(* Logix 5000 project; controller L32E vendor 1 type 14 code 65 rev 16.20; software revision 16.03 *)

TASK MainTask (continuous, watchdog 500 ms) : MainProgram

MODULES
   Controller : vendor 1 type 14 code 65 (CompactLogixL35Controller 0, rev 16.20)
      LocalENB : 1769-L35E Ethernet Port (CompactLogixL35Ethernet 1, rev 16.3)
      Local : CompactBus (CompactVirtualAdapter 3, rev 16.1, Input RPI 2 ms)
         DPS : 1769-MODULE (Compact 1, rev 1.1, Output RPI 2 ms)   // 1769-DPS
END_MODULES

TYPE APP_CONSTANT_PATTERN :   // Constant Values Used for DPV1 Alarm and ExtDiagData
STRUCT
   UserAlarmData : SINT[32];   // Constants for Alarm Data
END_STRUCT
END_TYPE

TYPE APP_DPV1_PROG_CONTROL :   // Program Control Bits
STRUCT
   MainInitDone : BOOL;   // Main Initialization Complete
   Dpv1ReadRespInProgress : BOOL;   // DPV1 Read Response in Progress
   Dpv1WriteRespInProgress : BOOL;   // DPV1 Write Response in Progress
   Dpv1AlarmReqSend : BOOL;   // DPV1 Alarm Request Flag
   Dpv1AlarmReqInProgress : BOOL;   // DPV1 Alarm Request in Progress
   DpsDiagReqSend : BOOL;   // DPS Diagnostics Request Flag
   DpsDiagReqInProgress : BOOL;   // DPS Diagnostic Request in Progress
   Reserved0 : BOOL;   // Reserved
   Reserved1 : BOOL;   // Reserved
   Reserved2 : BOOL;   // Reserved
   Reserved3 : BOOL;   // Reserved
   Reserved4 : BOOL;   // Reserved
   Reserved5 : BOOL;   // Reserved
   Reserved6 : BOOL;   // Reserved
   Reserved7 : BOOL;   // Reserved
   Reserved8 : BOOL;   // Reserved
   DPV1RWIndCnt : SINT;   // DPV1 R/W Indication Counter
END_STRUCT
END_TYPE

TYPE APP_DPV1_STAT_COUNTER :   // DPV1 Status Counter
STRUCT
   NumReadWrite : DINT;   // Number of DPV1 Read Write Response Sent
   ReadRespPos : DINT;   // Number of DPV1 Read Response Successful
   ReadRespNeg : DINT;   // Number of DPV1 Read Response Failed
   WriteRespPos : DINT;   // Number of DPV1 Write Response Successful
   WriteRespNeg : DINT;   // Number of DPV1 Write Response Failed
   NumAlarmRequest : DINT;   // Number of DPV1 Alarm Requests sent
   AlarmRequestPos : DINT;   // Number of DPV1 Alarm Requests Successful
   AlarmRequestNeg : DINT;   // Number of DPV1 Alarm Requests Failed
   NumDiagReq : DINT;   // Number of Diagnostic Reports Sent
   DiagReqPos : DINT;   // Number of Diagnostic Report Successful
   DiagReqNeg : DINT;   // Number of Diagnostic Report Failed
END_STRUCT
END_TYPE

TYPE DPS_DEV_COMMAND_REGISTER :   // Device Command Register
STRUCT
   Reserved0 : BOOL;   // Reserved
   Reserved1 : BOOL;   // Reserved
   Reserved2 : BOOL;   // Reserved
   Reserved3 : BOOL;   // Reserved
   Reserved4 : BOOL;   // Reserved
   NRdy : BOOL;   // Application Not Ready
   Init : BOOL;   // Init ( Warm boot )
   Reset : BOOL;   // Reset ( Cold boot )
   Reserved5 : SINT;   // Reserved
   Reserved6 : SINT;   // Reserved
   ExtStaSelect : SINT;   // Extra Status Select
END_STRUCT
END_TYPE

TYPE DPS_DEV_STATUS_REGISTER :   // Device Status Register
STRUCT
   Reserved0 : BOOL;   // Reserved
   Reserved1 : BOOL;   // Reserved
   Reserved2 : BOOL;   // Reserved
   Reserved3 : BOOL;   // Reserved
   Reserved4 : BOOL;   // Reserved
   Com : BOOL;   // Communication
   Run : BOOL;   // Running
   Rdy : BOOL;   // Ready
   Reserved5 : SINT;   // Reserved
   Reserved6 : SINT;   // Reserved
   Reserved7 : SINT;   // Reserved
END_STRUCT
END_TYPE

TYPE DPS_DIAGNOSTIC_CONFIRM :   // DPS Diagnostics Confirmation
STRUCT
   Reserved1 : INT;   // Reserved
   Reserved2 : INT;   // Reserved
   Answer : SINT;   // Answer of Diag Req
   Failure : SINT;   // Failure
   Reserved4 : INT;   // Reserved
   Reserved5 : INT;   // Reserved
   Reserved6 : INT;   // Reserved
   Reserved7 : SINT;   // Reserved
   ExtDiagDataCnt : SINT;   // Extended Diagnostics Data Count
   Mode : SINT;   // Mode
   Function : SINT;   // Function
END_STRUCT
END_TYPE

TYPE DPS_DIAGNOSTIC_REQUEST :   // DPS Diagnostics Request
STRUCT
   Reserved1 : INT;   // Reserved
   Reserved2 : INT;   // Reserved
   Reserved3 : INT;   // Reserved
   Command : SINT;   // Command for Diag Req = 24
   Reserved4 : SINT;   // Reserved
   Reserved5 : INT;   // Reserved
   Reserved6 : INT;   // Reserved
   Reserved7 : SINT;   // Reserved
   ExtDiagDataCnt : SINT;   // Number of ext. diag data
   Mode : SINT;   // Diag mode: (0 = default, 1 = suppress Ext.DiagBit)
   Function : SINT;   // Send diag once (fix 18)
   DiagData : SINT[32];   // Extended diag data (format see PROFIBUS Norm)
END_STRUCT
END_TYPE

TYPE DPS_DPV1C1_ALARM_CONFIRM :   // DPV1 Alarm Confirmation
STRUCT
   Reserved1 : INT;   // Reserved
   Reserved2 : INT;   // Reserved
   Answer : SINT;   // DPV1 Alarm Answer Flag
   Failure : SINT;   // DPV1 Alarm Failure
   Reserved3 : INT;   // Reserved
   Reserved4 : INT;   // Reserved
   SlotNumber : INT;   // DPV1 Alarm Slot Number
   SequenceNumber : SINT;   // DPV1 Alarm Sequence Number
   DataCnt : SINT;   // DPV1 Alarm Data Count
   AlarmType : SINT;   // DPV1 Alarm Type
   Specifier : SINT;   // DPV1 Alarm Specifier
END_STRUCT
END_TYPE

TYPE DPS_DPV1C1_ALARM_REQUEST :   // DPV1 Alarm Request
STRUCT
   Reserved1 : INT;   // Reserved
   Reserved2 : INT;   // Reserved
   Reserved3 : INT;   // Reserved
   Command : SINT;   // DPV1 Alarm Command
   Reserved4 : SINT;   // Reserved
   Reserved5 : INT;   // Reserved
   SlotNumber : INT;   // DPV1 Alarm Slot Number
   SequenceNumber : SINT;   // DPV1 Alarm Sequence Number
   DataCnt : SINT;   // DPV1 Alarm Data Count
   AlarmType : SINT;   // DPV1 Alarm Type
   Specifier : SINT;   // DPV1 Alarm Specifier
   AlarmData : SINT[28];   // DPV1 Alarm Data Array
END_STRUCT
END_TYPE

TYPE DPS_DPV1C1_RW_INDICATION :   // DPV1 C1 Read/Write Indication
STRUCT
   ReadReq : BOOL;   // Indicates a Read request
   WriteReq : BOOL;   // Indicates a Write request
   Reserved2 : BOOL;   // Reserved
   Reserved3 : BOOL;   // Reserved
   Reserved4 : BOOL;   // Reserved
   Reserved5 : BOOL;   // Reserved
   Reserved6 : BOOL;   // Reserved
   Reserved7 : BOOL;   // Reserved
   RwCnt : SINT;   // ReadWrite indication counter
   MaAdr : SINT;   // Address of reqesting master
   Slot : SINT;   // Requested Slot Number
   Index : SINT;   // Requested Index
   DataLen : SINT;   // Requested Data Length
   Reserved8 : SINT;   // Reserved
   Reserved9 : SINT;   // Reserved
END_STRUCT
END_TYPE

TYPE DPS_DPV1C1_RW_RESP_CONFIRM :   // DPV1 Class 1 Read/Write Confirmation
STRUCT
   Reserved1 : INT;   // Reserved
   Reserved2 : INT;   // Reserved
   Answer : SINT;   // DPV1 R/W Answer
   Failure : SINT;   // DPV1 R/W Failure
   Reserved3 : INT;   // Reserved
   RwResp : SINT;   // Read Resp (=1) or Write Resp (=2)
   Reserved4 : SINT;   // Reserved
   MaAdr : SINT;   // Reply of reqesting Master Address
   Slot : SINT;   // Reply of requested Slot Number
   Index : SINT;   // Reply of requested Index
   DataLen : SINT;   // Number of requested data
   ErrCode1 : SINT;   // Reply of Error code 1 according to DPV1
   ErrCode2 : SINT;   // Reply of Error code 2 according to DPV1
   RWRespData : SINT[240];   // DPV1 Write data
END_STRUCT
END_TYPE

TYPE DPS_DPV1C1_RW_RESP_REQUEST :   // DPV1 Class 1 Read/Write Response Request
STRUCT
   Reserved1 : INT;   // Reserved
   Reserved2 : INT;   // Reserved
   Reserved3 : INT;   // Reserved
   Command : SINT;   // DPV1 ReadWrite Resp. Request (=17)
   Reserved4 : SINT;   // Reserved
   RwResp : SINT;   // Read Resp (=1) or Write Resp (=2)
   Reserved5 : SINT;   // Reserved
   MaAdr : SINT;   // Reply of reqesting Master Address
   Slot : SINT;   // Reply of requested Slot Number
   Index : SINT;   // Reply of requested Index
   DataLen : SINT;   // Reply of requested number of data
   ErrCode1 : SINT;   // Error code 1 according to DPV1
   ErrCode2 : SINT;   // Error code 2 according to DPV1
   RWRespData : SINT[240];   // DPV1 Read response data
END_STRUCT
END_TYPE

TYPE DPS_FW_REVISION :   // Firmware Major/Minor Revision
STRUCT
   FwMinor : SINT;   // Firmware Minor Revison
   FwMajor : SINT;   // Firmware Major Revison
   Reserved : INT;   // Reserved
END_STRUCT
END_TYPE

TYPE DPS_INPUT_ARRAY :   // DPS Input Array
STRUCT
   DevStaReg : DPS_DEV_STATUS_REGISTER;   // Device Status Registers
   FwRev : DPS_FW_REVISION;   // Firmware Revision
   StaField : DPS_STATUS_FIELD;   // DPS Status Registers
   PBOutputData : SINT[380];   // PROFIBUS Output Data from Matser
END_STRUCT
END_TYPE

TYPE DPS_MODULE_DEF :
STRUCT
   AppConstPattern : APP_CONSTANT_PATTERN;   // Constant Values used for DPV1 Alarm and ExtDiagData
   AppCtrl : APP_DPV1_PROG_CONTROL;   // Program Control Bits
   AppStatCnt : APP_DPV1_STAT_COUNTER;   // DPV1 Status Counter
   DiagCnf : DPS_DIAGNOSTIC_CONFIRM;   // DPS Diagnostics Confirmation
   DiagReq : DPS_DIAGNOSTIC_REQUEST;   // DPS Diagnostics Request
   DpsInputArray : DPS_INPUT_ARRAY;   // DPS Input Array
   DpsOutputArray : DPS_OUTPUT_ARRAY;   // DPS Output Array
   Dpv1AlarmCnf : DPS_DPV1C1_ALARM_CONFIRM;   // DPV1 Alarm Confirmation
   Dpv1AlarmReq : DPS_DPV1C1_ALARM_REQUEST;   // DPV1 Alarm Request
   DPV1RWDataBuffer : SINT[240];   // Buffer for DPV1 Data
   Dpv1RWRespCnf : DPS_DPV1C1_RW_RESP_CONFIRM;   // DPV1 Class 1 Read/Write Confirmation
   Dpv1RWRespReq : DPS_DPV1C1_RW_RESP_REQUEST;   // DPV1 Class 1 Read/Write Response Request
END_STRUCT
END_TYPE

TYPE DPS_OUTPUT_ARRAY :   // DPS Output Array
STRUCT
   DevCmdReg : DPS_DEV_COMMAND_REGISTER;   // Device Command Register
   PBInputData : SINT[244];   // PROFIBIBUS Input Data for Master
END_STRUCT
END_TYPE

TYPE DPS_STATUS_FIELD :   // DPS Status Field
STRUCT
   ExtStaSelect : INT;   // Extended Status Select
   ExtStaLen : INT;   // Extended Status Length
   Baudrate : INT;   // Slave Baudrate
   Busaddress : SINT;   // Slave Bus Address
   UserFlags : SINT;   // User Flags
   Ident : INT;   // Slave Ident Number
   TaskState : INT;   // Slave Task State
   InputDataLen : INT;   // Slave Input Data Length
   OutputDataLen : INT;   // Slave Output Data Length
   ErrorCount : INT;   // Slave Error Count
   LastError : SINT;   // Slave Last Error
   Pad : SINT;   // Reserved
   WatchdogTime : INT;   // Slave Watchdog Time
   IrqCounter : INT;   // Slave Interrupt Counter
   C1Ind : DPS_DPV1C1_RW_INDICATION;   // DPV1 Class 1 Indication Registers
   ExtStatusInfo : SINT[96];   // Extened Status Information
END_STRUCT
END_TYPE

ADD_ON_INSTRUCTION AOIPS69DPS   (* revision 1.1 *)
// Add-On instruction for the PS69-DPS module
// Revision note:
// Added viewing capability for the Add_On Instruction
VAR_IN_OUT
   Connection_Input : INT[190]; {required}   // Connect to module input image
   Connection_Output : INT[124]; {required}   // Connect to module output image
   PS69DPS : DPS_MODULE_DEF; {required}   // Main controller tag
   DiagReqMsg : MESSAGE; {required}
   Dpv1AlarmMsg : MESSAGE; {required}
   Dpv1RWMsg : MESSAGE; {required}
END_VAR

ROUTINE Logic   (* ladder *)
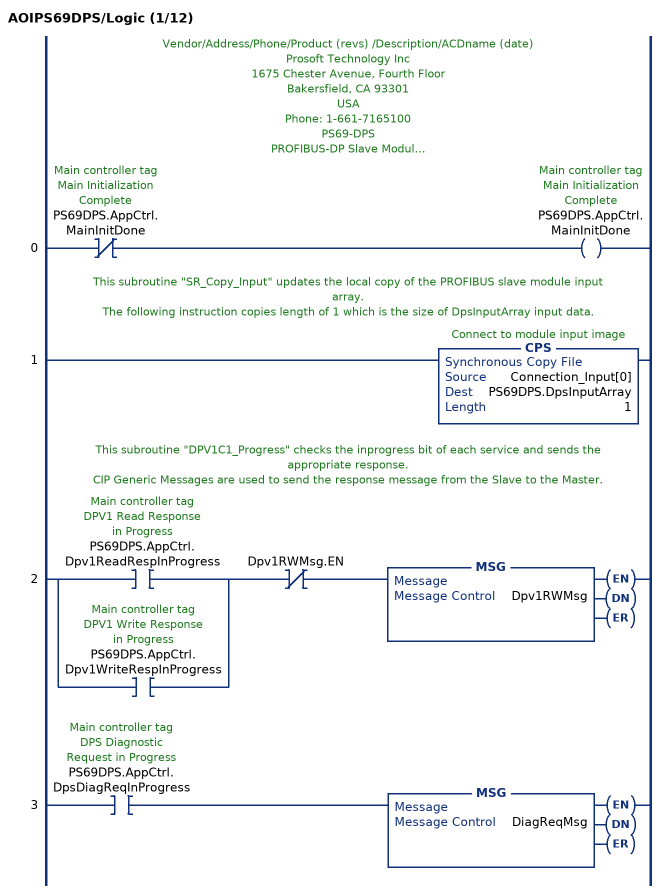
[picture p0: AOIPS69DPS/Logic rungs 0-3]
   // Vendor/Address/Phone/Product (revs) /Description/ACDname (date)
   // Prosoft Technology Inc
   // 1675 Chester Avenue, Fourth Floor
   // Bakersfield, CA 93301
   // USA
   // Phone: 1-661-7165100
   // PS69-DPS
   // PROFIBUS-DP Slave Module
   // PS69_DPS_messaging_L32E.ACD (Rev1.0) (07/28/05)
   // Although this program has been developed with great care and intensively tested,
   // Prosoft Technology Inc cannot guarantee the suitability of this program
   // for any purpose not confirmed by us in writing.
   // We reserve the right to modify our products and their specifications at any time in as far as this contributes to technical progress.
   // The version of the manual supplied with the program applies.
   // This program is a basic example RSLogix5000 project used for sending PROFIBUS messages to the communication module "PS69-DPS". This project provides an example for every supported PROFIBUS message by the module.
   // For detailed information about the these messages (functionality, parameters, error codes etc. ) refer to the module User Manual document.
   // This Rung calls all init routines for one time, to initialize the PROFIBUS commands.
   0: XIO(PS69DPS.AppCtrl.MainInitDone)OTE(PS69DPS.AppCtrl.MainInitDone);
   // This subroutine "SR_Copy_Input" updates the local copy of the PROFIBUS slave module input array.
   // The following instruction copies length of 1 which is the size of DpsInputArray input data.
   1: CPS(Connection_Input[0],PS69DPS.DpsInputArray,1);
   // This subroutine "DPV1C1_Progress" checks the inprogress bit of each service and sends the appropriate response.
   // CIP Generic Messages are used to send the response message from the Slave to the Master.
   2: [XIC(PS69DPS.AppCtrl.Dpv1ReadRespInProgress) ,XIC(PS69DPS.AppCtrl.Dpv1WriteRespInProgress) ]XIO(Dpv1RWMsg.EN)MSG(Dpv1RWMsg);
   3: XIC(PS69DPS.AppCtrl.DpsDiagReqInProgress)MSG(DiagReqMsg);
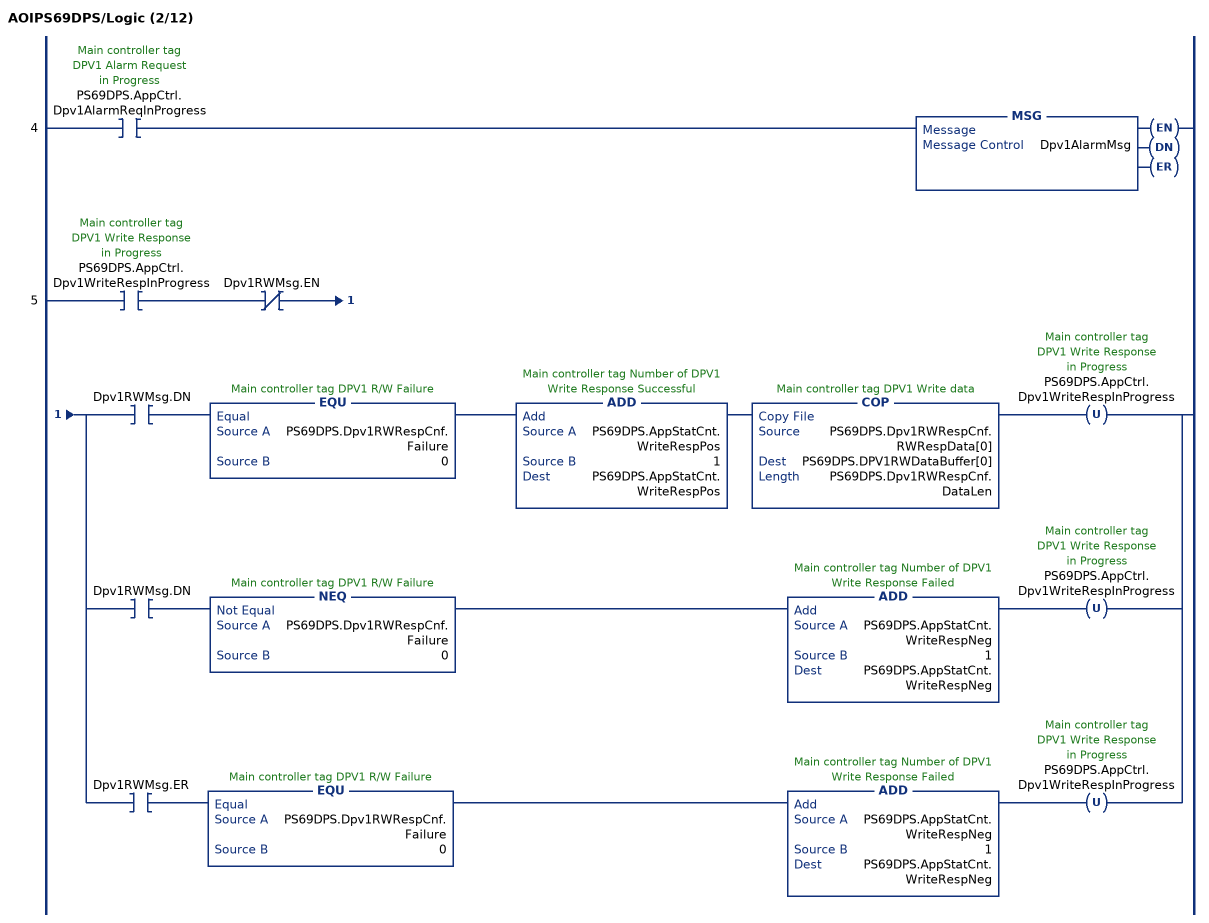
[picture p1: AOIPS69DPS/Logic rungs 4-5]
   4: XIC(PS69DPS.AppCtrl.Dpv1AlarmReqInProgress)MSG(Dpv1AlarmMsg);
   5: XIC(PS69DPS.AppCtrl.Dpv1WriteRespInProgress)XIO(Dpv1RWMsg.EN)[XIC(Dpv1RWMsg.DN) EQU(PS69DPS.Dpv1RWRespCnf.Failure,0) ADD(PS69DPS.AppStatCnt.WriteRespPos,1,PS69DPS.AppStatCnt.WriteRespPos) COP(PS69DPS.Dpv1RWRespCnf.RWRespData[0],PS69DPS.DPV1RWDataBuffer[0],PS69DPS.Dpv1RWRespCnf.DataLen) OTU(PS69DPS.AppCtrl.Dpv1WriteRespInProgress) ,XIC(Dpv1RWMsg.DN) NEQ(PS69DPS.Dpv1RWRespCnf.Failure,0) ADD(PS69DPS.AppStatCnt.WriteRespNeg,1,PS69DPS.AppStatCnt.WriteRespNeg) OTU(PS69DPS.AppCtrl.Dpv1WriteRespInProgress) ,XIC(Dpv1RWMsg.ER) EQU(PS69DPS.Dpv1RWRespCnf.Failure,0) ADD(PS69DPS.AppStatCnt.WriteRespNeg,1,PS69DPS.AppStatCnt.WriteRespNeg) OTU(PS69DPS.AppCtrl.Dpv1WriteRespInProgress) ];
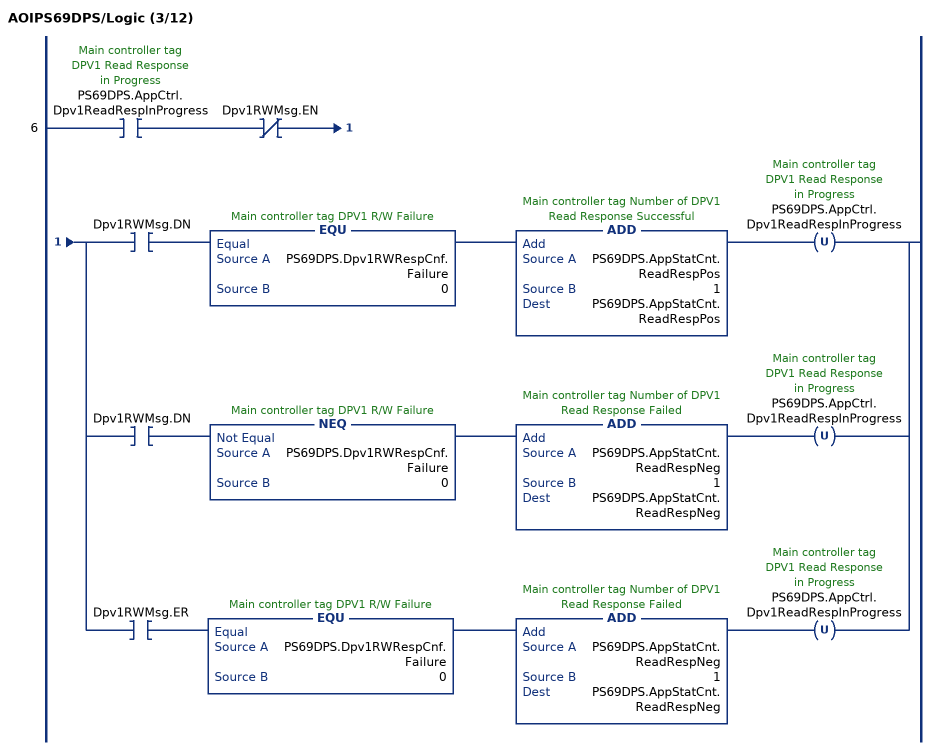
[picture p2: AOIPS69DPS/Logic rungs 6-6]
   6: XIC(PS69DPS.AppCtrl.Dpv1ReadRespInProgress)XIO(Dpv1RWMsg.EN)[XIC(Dpv1RWMsg.DN) EQU(PS69DPS.Dpv1RWRespCnf.Failure,0) ADD(PS69DPS.AppStatCnt.ReadRespPos,1,PS69DPS.AppStatCnt.ReadRespPos) OTU(PS69DPS.AppCtrl.Dpv1ReadRespInProgress) ,XIC(Dpv1RWMsg.DN) NEQ(PS69DPS.Dpv1RWRespCnf.Failure,0) ADD(PS69DPS.AppStatCnt.ReadRespNeg,1,PS69DPS.AppStatCnt.ReadRespNeg) OTU(PS69DPS.AppCtrl.Dpv1ReadRespInProgress) ,XIC(Dpv1RWMsg.ER) EQU(PS69DPS.Dpv1RWRespCnf.Failure,0) ADD(PS69DPS.AppStatCnt.ReadRespNeg,1,PS69DPS.AppStatCnt.ReadRespNeg) OTU(PS69DPS.AppCtrl.Dpv1ReadRespInProgress) ];
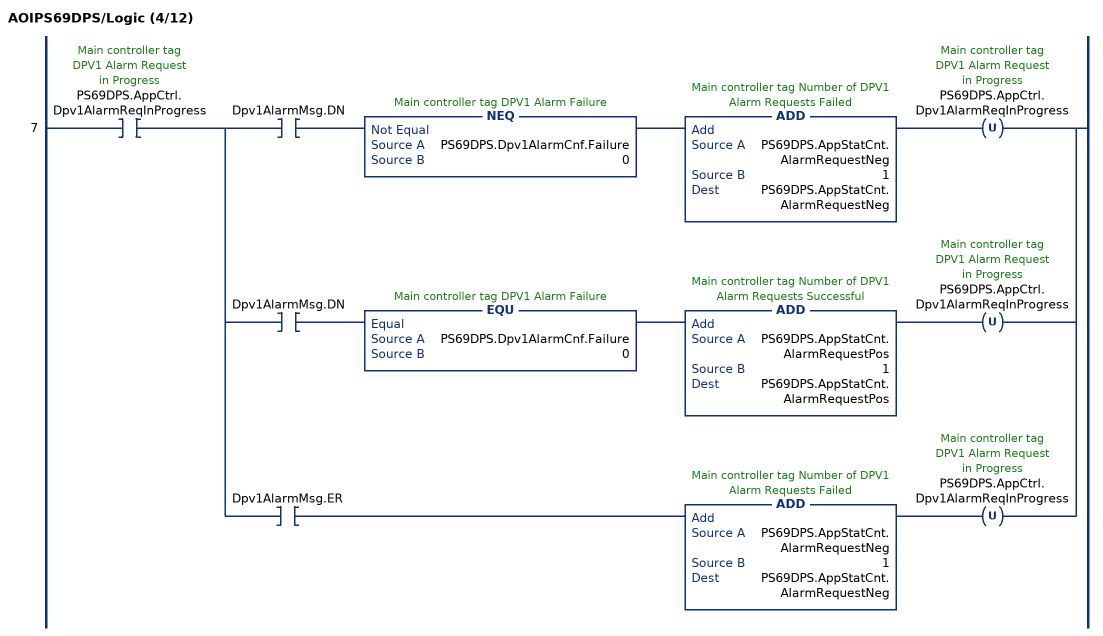
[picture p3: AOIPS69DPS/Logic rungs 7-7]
   7: XIC(PS69DPS.AppCtrl.Dpv1AlarmReqInProgress)[XIC(Dpv1AlarmMsg.DN) NEQ(PS69DPS.Dpv1AlarmCnf.Failure,0) ADD(PS69DPS.AppStatCnt.AlarmRequestNeg,1,PS69DPS.AppStatCnt.AlarmRequestNeg) OTU(PS69DPS.AppCtrl.Dpv1AlarmReqInProgress) ,XIC(Dpv1AlarmMsg.DN) EQU(PS69DPS.Dpv1AlarmCnf.Failure,0) ADD(PS69DPS.AppStatCnt.AlarmRequestPos,1,PS69DPS.AppStatCnt.AlarmRequestPos) OTU(PS69DPS.AppCtrl.Dpv1AlarmReqInProgress) ,XIC(Dpv1AlarmMsg.ER) ADD(PS69DPS.AppStatCnt.AlarmRequestNeg,1,PS69DPS.AppStatCnt.AlarmRequestNeg) OTU(PS69DPS.AppCtrl.Dpv1AlarmReqInProgress) ];
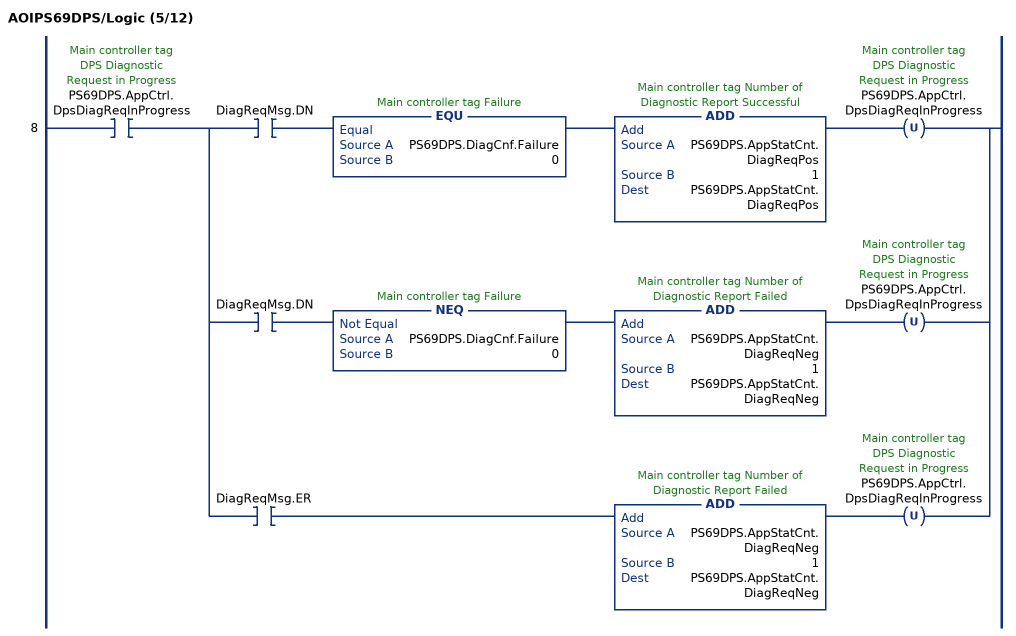
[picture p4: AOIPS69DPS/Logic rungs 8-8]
   8: XIC(PS69DPS.AppCtrl.DpsDiagReqInProgress)[XIC(DiagReqMsg.DN) EQU(PS69DPS.DiagCnf.Failure,0) ADD(PS69DPS.AppStatCnt.DiagReqPos,1,PS69DPS.AppStatCnt.DiagReqPos) OTU(PS69DPS.AppCtrl.DpsDiagReqInProgress) ,XIC(DiagReqMsg.DN) NEQ(PS69DPS.DiagCnf.Failure,0) ADD(PS69DPS.AppStatCnt.DiagReqNeg,1,PS69DPS.AppStatCnt.DiagReqNeg) OTU(PS69DPS.AppCtrl.DpsDiagReqInProgress) ,XIC(DiagReqMsg.ER) ADD(PS69DPS.AppStatCnt.DiagReqNeg,1,PS69DPS.AppStatCnt.DiagReqNeg) OTU(PS69DPS.AppCtrl.DpsDiagReqInProgress) ];
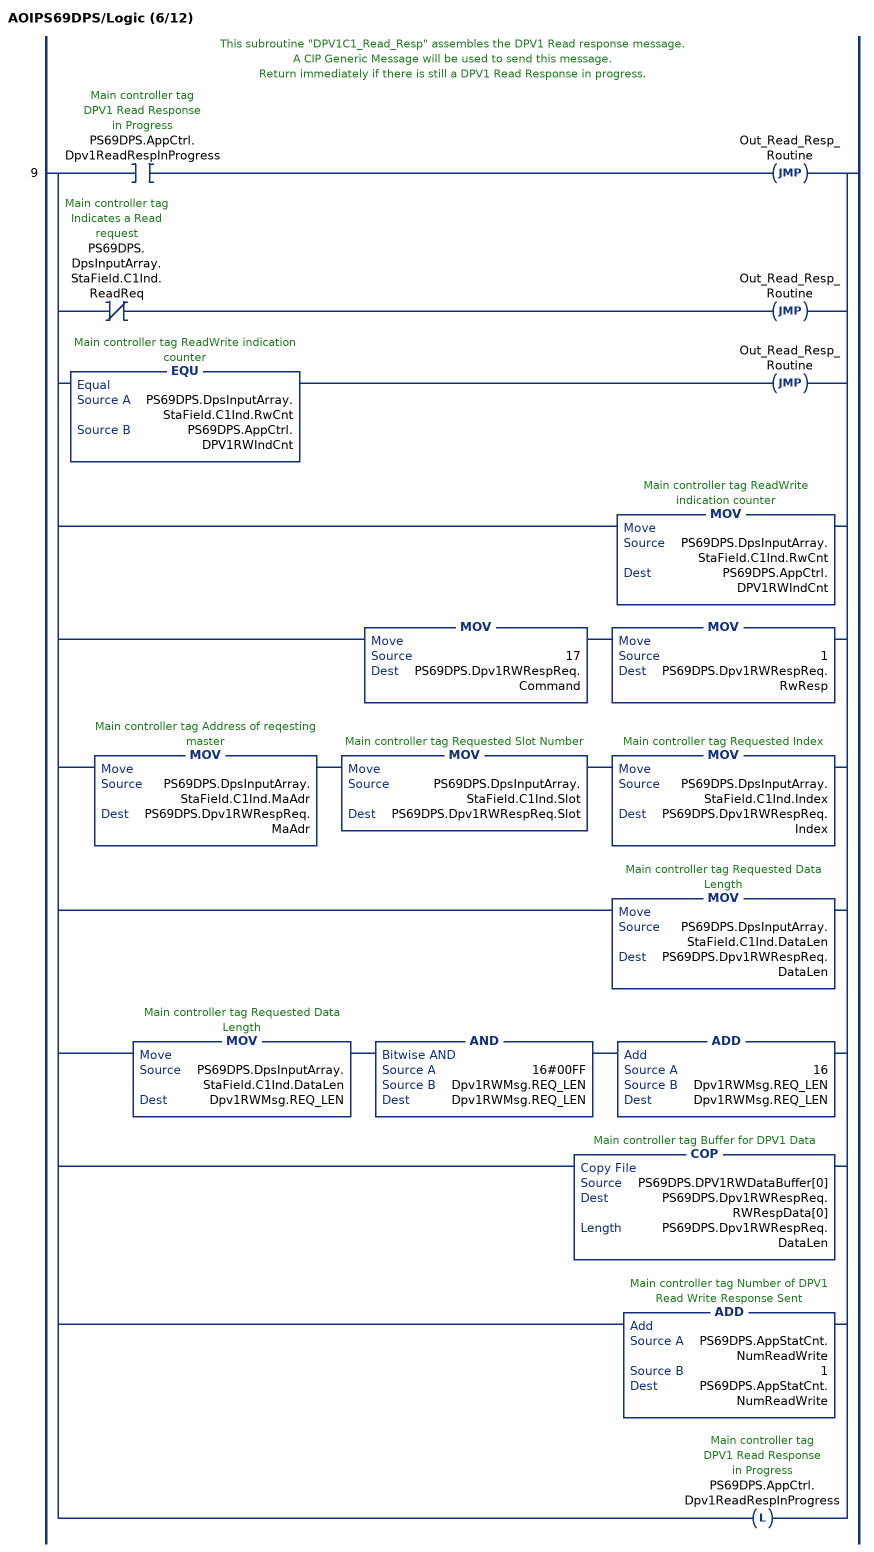
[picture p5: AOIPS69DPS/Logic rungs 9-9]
   // This subroutine "DPV1C1_Read_Resp" assembles the DPV1 Read response message.
   // A CIP Generic Message will be used to send this message.
   // Return immediately if there is still a DPV1 Read Response in progress.
   9: [XIC(PS69DPS.AppCtrl.Dpv1ReadRespInProgress) JMP(Out_Read_Resp_Routine) ,XIO(PS69DPS.DpsInputArray.StaField.C1Ind.ReadReq) JMP(Out_Read_Resp_Routine) ,EQU(PS69DPS.DpsInputArray.StaField.C1Ind.RwCnt,PS69DPS.AppCtrl.DPV1RWIndCnt) JMP(Out_Read_Resp_Routine) ,MOV(PS69DPS.DpsInputArray.StaField.C1Ind.RwCnt,PS69DPS.AppCtrl.DPV1RWIndCnt) ,MOV(17,PS69DPS.Dpv1RWRespReq.Command) MOV(1,PS69DPS.Dpv1RWRespReq.RwResp) ,MOV(PS69DPS.DpsInputArray.StaField.C1Ind.MaAdr,PS69DPS.Dpv1RWRespReq.MaAdr) MOV(PS69DPS.DpsInputArray.StaField.C1Ind.Slot,PS69DPS.Dpv1RWRespReq.Slot) MOV(PS69DPS.DpsInputArray.StaField.C1Ind.Index,PS69DPS.Dpv1RWRespReq.Index) ,MOV(PS69DPS.DpsInputArray.StaField.C1Ind.DataLen,PS69DPS.Dpv1RWRespReq.DataLen) ,MOV(PS69DPS.DpsInputArray.StaField.C1Ind.DataLen,Dpv1RWMsg.REQ_LEN) AND(16#00FF,Dpv1RWMsg.REQ_LEN,Dpv1RWMsg.REQ_LEN) ADD(16,Dpv1RWMsg.REQ_LEN,Dpv1RWMsg.REQ_LEN) ,COP(PS69DPS.DPV1RWDataBuffer[0],PS69DPS.Dpv1RWRespReq.RWRespData[0],PS69DPS.Dpv1RWRespReq.DataLen) ,ADD(PS69DPS.AppStatCnt.NumReadWrite,1,PS69DPS.AppStatCnt.NumReadWrite) ,OTL(PS69DPS.AppCtrl.Dpv1ReadRespInProgress) ];
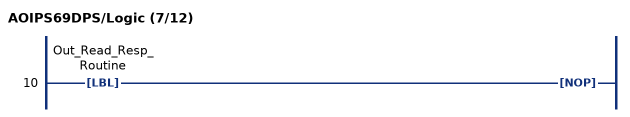
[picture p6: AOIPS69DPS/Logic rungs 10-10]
   10: LBL(Out_Read_Resp_Routine)NOP();
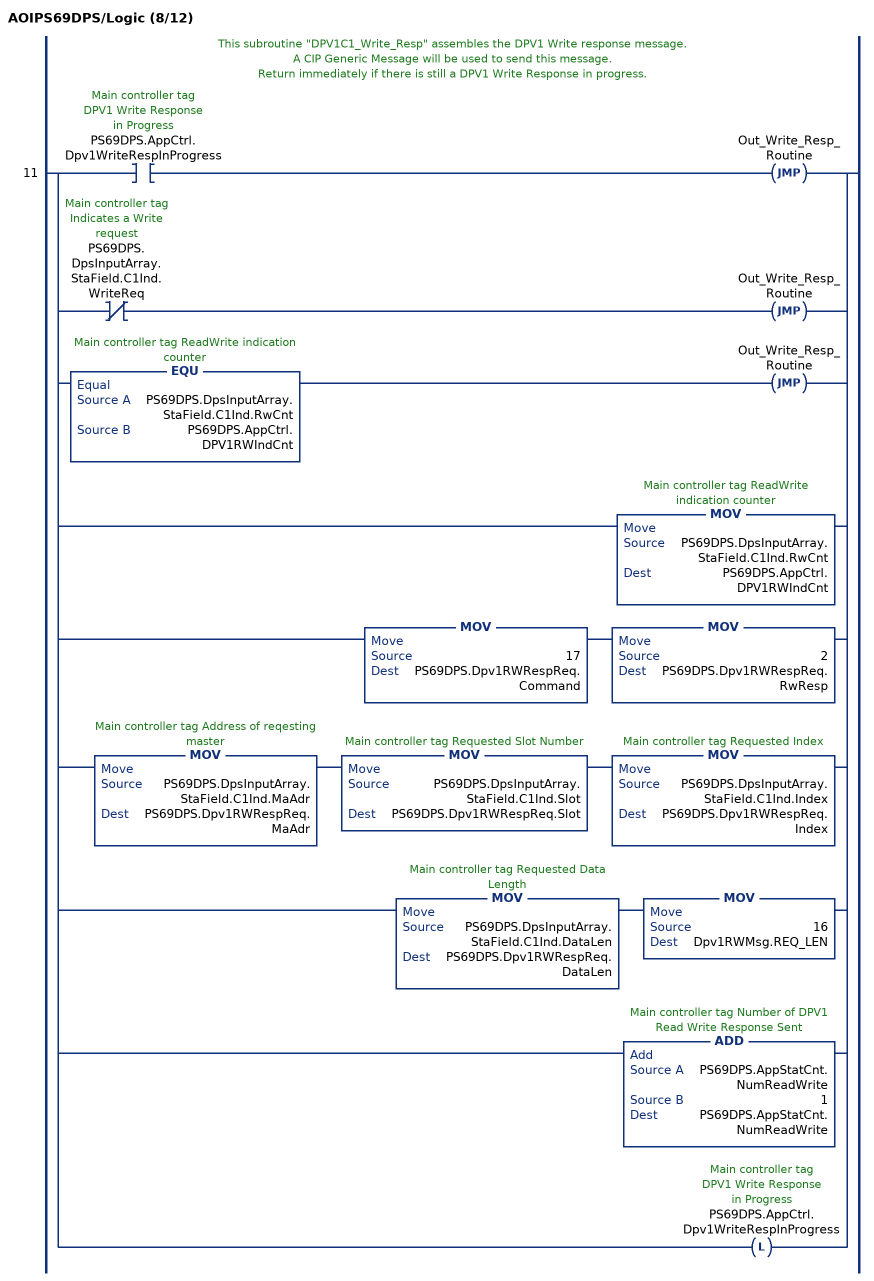
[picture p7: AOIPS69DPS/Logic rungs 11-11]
   // This subroutine "DPV1C1_Write_Resp" assembles the DPV1 Write response message.
   // A CIP Generic Message will be used to send this message.
   // Return immediately if there is still a DPV1 Write Response in progress.
   11: [XIC(PS69DPS.AppCtrl.Dpv1WriteRespInProgress) JMP(Out_Write_Resp_Routine) ,XIO(PS69DPS.DpsInputArray.StaField.C1Ind.WriteReq) JMP(Out_Write_Resp_Routine) ,EQU(PS69DPS.DpsInputArray.StaField.C1Ind.RwCnt,PS69DPS.AppCtrl.DPV1RWIndCnt) JMP(Out_Write_Resp_Routine) ,MOV(PS69DPS.DpsInputArray.StaField.C1Ind.RwCnt,PS69DPS.AppCtrl.DPV1RWIndCnt) ,MOV(17,PS69DPS.Dpv1RWRespReq.Command) MOV(2,PS69DPS.Dpv1RWRespReq.RwResp) ,MOV(PS69DPS.DpsInputArray.StaField.C1Ind.MaAdr,PS69DPS.Dpv1RWRespReq.MaAdr) MOV(PS69DPS.DpsInputArray.StaField.C1Ind.Slot,PS69DPS.Dpv1RWRespReq.Slot) MOV(PS69DPS.DpsInputArray.StaField.C1Ind.Index,PS69DPS.Dpv1RWRespReq.Index) ,MOV(PS69DPS.DpsInputArray.StaField.C1Ind.DataLen,PS69DPS.Dpv1RWRespReq.DataLen) MOV(16,Dpv1RWMsg.REQ_LEN) ,ADD(PS69DPS.AppStatCnt.NumReadWrite,1,PS69DPS.AppStatCnt.NumReadWrite) ,OTL(PS69DPS.AppCtrl.Dpv1WriteRespInProgress) ];
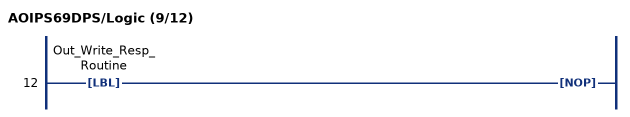
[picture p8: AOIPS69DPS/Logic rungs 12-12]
   12: LBL(Out_Write_Resp_Routine)NOP();
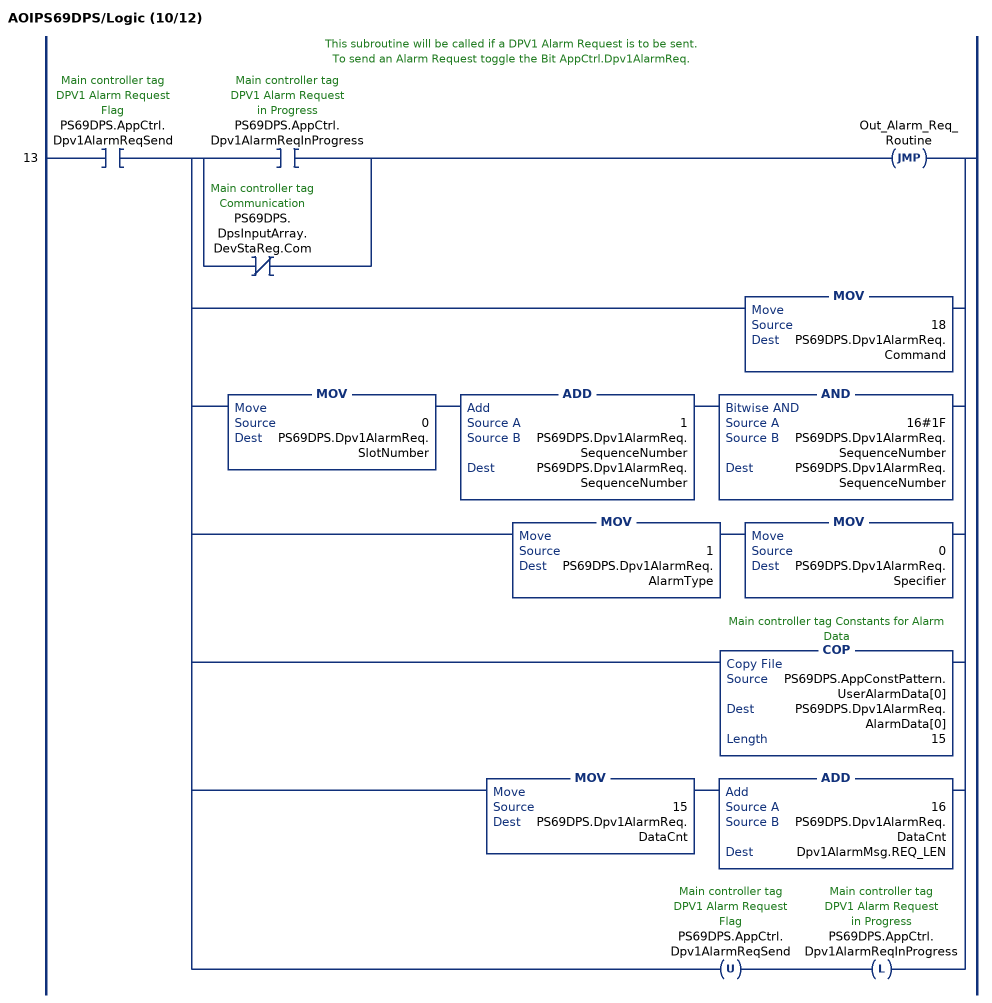
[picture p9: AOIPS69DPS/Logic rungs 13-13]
   // This subroutine will be called if a DPV1 Alarm Request is to be sent.
   // To send an Alarm Request toggle the Bit AppCtrl.Dpv1AlarmReq.
   13: XIC(PS69DPS.AppCtrl.Dpv1AlarmReqSend)[[XIC(PS69DPS.AppCtrl.Dpv1AlarmReqInProgress) ,XIO(PS69DPS.DpsInputArray.DevStaReg.Com) ] JMP(Out_Alarm_Req_Routine) ,MOV(18,PS69DPS.Dpv1AlarmReq.Command) ,MOV(0,PS69DPS.Dpv1AlarmReq.SlotNumber) ADD(1,PS69DPS.Dpv1AlarmReq.SequenceNumber,PS69DPS.Dpv1AlarmReq.SequenceNumber) AND(16#1F,PS69DPS.Dpv1AlarmReq.SequenceNumber,PS69DPS.Dpv1AlarmReq.SequenceNumber) ,MOV(1,PS69DPS.Dpv1AlarmReq.AlarmType) MOV(0,PS69DPS.Dpv1AlarmReq.Specifier) ,COP(PS69DPS.AppConstPattern.UserAlarmData[0],PS69DPS.Dpv1AlarmReq.AlarmData[0],15) ,MOV(15,PS69DPS.Dpv1AlarmReq.DataCnt) ADD(16,PS69DPS.Dpv1AlarmReq.DataCnt,Dpv1AlarmMsg.REQ_LEN) ,OTU(PS69DPS.AppCtrl.Dpv1AlarmReqSend) OTL(PS69DPS.AppCtrl.Dpv1AlarmReqInProgress) ];
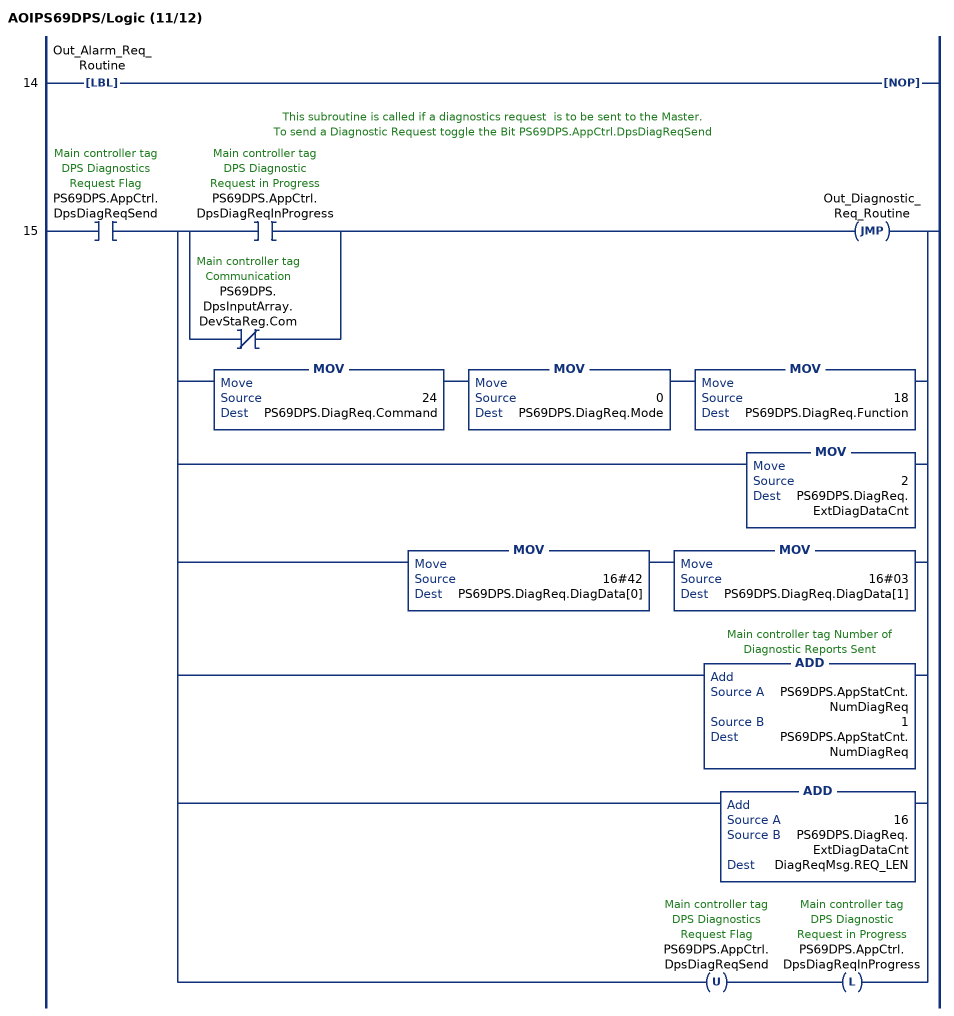
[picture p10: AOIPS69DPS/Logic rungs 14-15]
   14: LBL(Out_Alarm_Req_Routine)NOP();
   // This subroutine is called if a diagnostics request  is to be sent to the Master.
   // To send a Diagnostic Request toggle the Bit PS69DPS.AppCtrl.DpsDiagReqSend
   15: XIC(PS69DPS.AppCtrl.DpsDiagReqSend)[[XIC(PS69DPS.AppCtrl.DpsDiagReqInProgress) ,XIO(PS69DPS.DpsInputArray.DevStaReg.Com) ] JMP(Out_Diagnostic_Req_Routine) ,MOV(24,PS69DPS.DiagReq.Command) MOV(0,PS69DPS.DiagReq.Mode) MOV(18,PS69DPS.DiagReq.Function) ,MOV(2,PS69DPS.DiagReq.ExtDiagDataCnt) ,MOV(16#42,PS69DPS.DiagReq.DiagData[0]) MOV(16#03,PS69DPS.DiagReq.DiagData[1]) ,ADD(PS69DPS.AppStatCnt.NumDiagReq,1,PS69DPS.AppStatCnt.NumDiagReq) ,ADD(16,PS69DPS.DiagReq.ExtDiagDataCnt,DiagReqMsg.REQ_LEN) ,OTU(PS69DPS.AppCtrl.DpsDiagReqSend) OTL(PS69DPS.AppCtrl.DpsDiagReqInProgress) ];
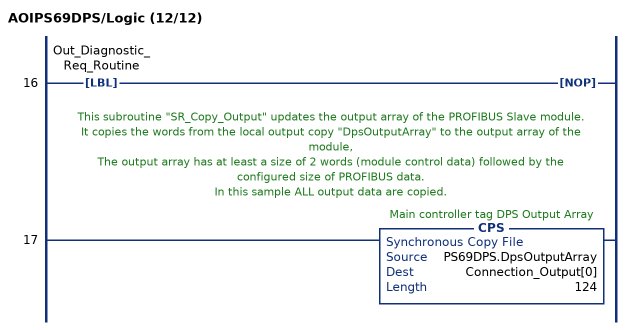
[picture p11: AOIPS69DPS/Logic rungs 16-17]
   16: LBL(Out_Diagnostic_Req_Routine)NOP();
   // This subroutine "SR_Copy_Output" updates the output array of the PROFIBUS Slave module.
   // It copies the words from the local output copy "DpsOutputArray" to the output array of the module,
   // The output array has at least a size of 2 words (module control data) followed by the configured size of PROFIBUS data.
   // In this sample ALL output data are copied.
   17: CPS(PS69DPS.DpsOutputArray,Connection_Output[0],124);
END_ROUTINE
END_ADD_ON_INSTRUCTION

VAR_GLOBAL   (* controller tags *)
   AOIPS69DPS : AOIPS69DPS;
   Connection_Input : INT[190];
   Connection_Output : INT[124];
   DiagReqMsg : MESSAGE;
        MessageParameters(ServiceCode := 16#0064, LocalElement := PS69DPS.DiagReq, DestinationTag := PS69DPS.DiagCnf, ...)
   Dpv1AlarmMsg : MESSAGE;
        MessageParameters(ServiceCode := 16#0064, LocalElement := PS69DPS.Dpv1AlarmReq, DestinationTag := PS69DPS.Dpv1AlarmCnf, ...)
   Dpv1RWMsg : MESSAGE;
        MessageParameters(ServiceCode := 16#0064, LocalElement := PS69DPS.Dpv1RWRespReq, DestinationTag := PS69DPS.Dpv1RWRespCnf, ...)
   PS69DPS : DPS_MODULE_DEF;
END_VAR

PROGRAM MainProgram   (* main routine MainRoutine *)

ROUTINE MainRoutine   (* ladder *)
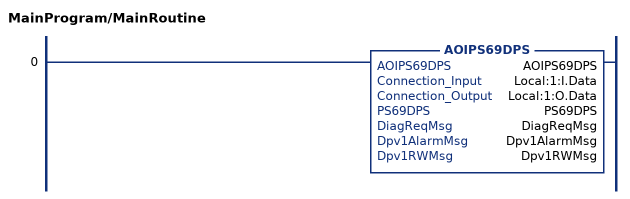
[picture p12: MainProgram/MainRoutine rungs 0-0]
   0: AOIPS69DPS(AOIPS69DPS,Local:1:I.Data,Local:1:O.Data,PS69DPS,DiagReqMsg,Dpv1AlarmMsg,Dpv1RWMsg);
END_ROUTINE
END_PROGRAM
